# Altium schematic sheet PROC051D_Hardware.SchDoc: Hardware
size 431 x 279 mm; Date: Not shown in title block; ApprovedBy: Not shown in title block; CheckedBy: Not shown in title block; Author: Not shown in title block; CompanyName: Not shown in title block; Engineer: Not shown in title block; Organization: Not shown in title block; Address1: Not shown in title block; Address2: Not shown in title block; Address3: Not shown in title block; Address4: Not shown in title block; DocumentNumber: 16; Revision: Use project parameter SCH_Rev; SheetNumber: 16; SheetTotal: 16; PageSetup: Record=PageOptions¦CenterHorizontal=True¦CenterVertical=True¦PrintScale=1.00¦XCorrection=1.00¦YCorrection=1.00¦PrintKind=0¦BorderSize=5000000¦LeftOffset=0¦BottomOffset=0¦Orientation=2¦PaperLength=1000¦PaperWidth=1000¦Scale=100¦PaperSource=15¦PrintQuality=600¦MediaType=1¦DitherType=10¦PaperKind=Letter¦PrintScaleMode=1
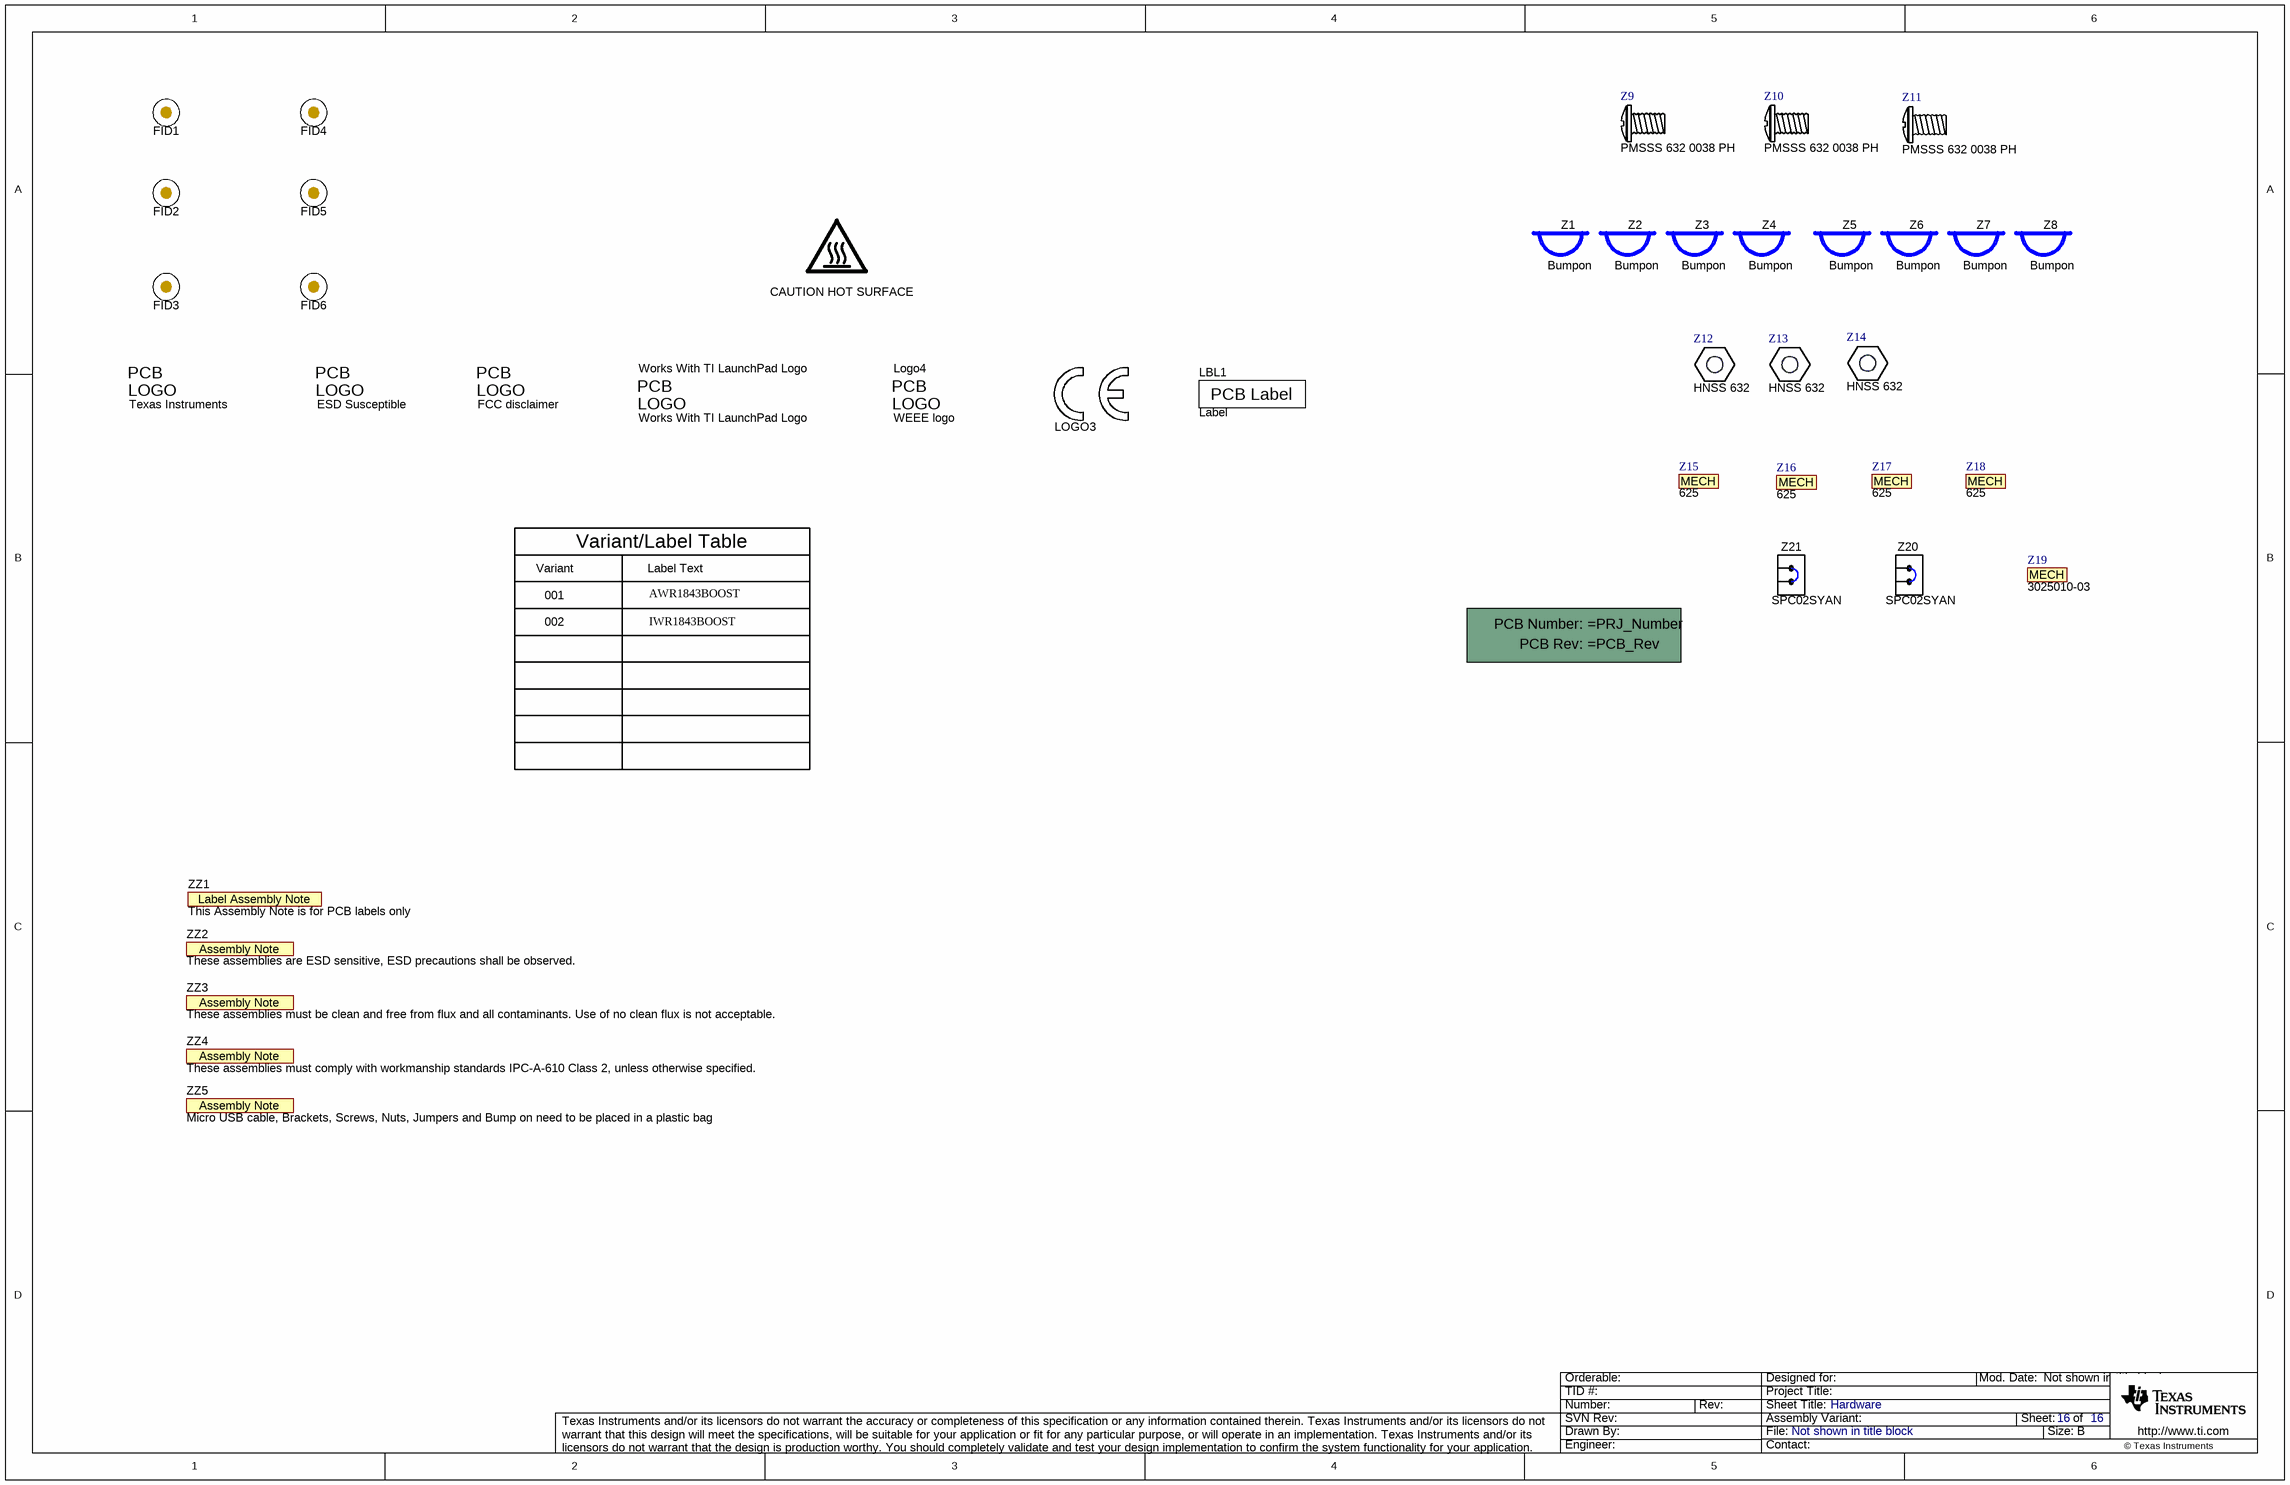
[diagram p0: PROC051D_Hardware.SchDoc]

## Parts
!PCB  PROC051  (value not drawn)  (mechanical)
CAUTION_HOT_SURFACE  CAUTION HOT SURFACE  [IEC_HotSurface_Small]  (no BOM)
ESD_Susceptible  ESD Susceptible  [ESD_Overlay_Small]  (no BOM)
FID1  Fiducial  [Fiducial10-20]  (value not drawn)
FID2  Fiducial  [Fiducial10-20]  (value not drawn)
FID3  Fiducial  [Fiducial10-20]  (value not drawn)
FID4  Fiducial  [Fiducial10-20]  (value not drawn)
FID5  Fiducial  [Fiducial10-20]  (value not drawn)
FID6  Fiducial  [Fiducial10-20]  (value not drawn)
LBL1  Label  [Label_650x200]
Logo1  Texas Instruments  [TI_Stacked_Overlay_Small]  (no BOM)
Logo2  FCC disclaimer  [FCC_disclaimer]  (no BOM)
LOGO3  CE Mark  [CE_Mark_5mm]  (value not drawn)  (no BOM)
Logo4  WEEE logo  [WEEE_Minimum]  (no BOM)
Works_With_TI_LaunchPad_Logo  Works With TI LaunchPad Logo  [WorksWithTILaunchPad]  (graphical)
Z1  Bumpon  [Bumpon_SJ61A1]  (mechanical)
Z2  Bumpon  [Bumpon_SJ61A1]  (mechanical)
Z3  Bumpon  [Bumpon_SJ61A1]  (mechanical)
Z4  Bumpon  [Bumpon_SJ61A1]  (mechanical)
Z5  Bumpon  [Bumpon_SJ61A1]  (mechanical)
Z6  Bumpon  [Bumpon_SJ61A1]  (mechanical)
Z7  Bumpon  [Bumpon_SJ61A1]  (mechanical)
Z8  Bumpon  [Bumpon_SJ61A1]  (mechanical)
Z9  PMSSS 632 0038 PH  [B-F_PMSSS_632_0038_PH]  (mechanical)
Z10  PMSSS 632 0038 PH  [B-F_PMSSS_632_0038_PH]  (mechanical)
Z11  PMSSS 632 0038 PH  [B-F_PMSSS_632_0038_PH]  (mechanical)
Z12  HNSS 632  [B-F_HNSS-632]  (mechanical)
Z13  HNSS 632  [B-F_HNSS-632]  (mechanical)
Z14  HNSS 632  [B-F_HNSS-632]  (mechanical)
Z15  625  (mechanical)
Z16  625  (mechanical)
Z17  625  (mechanical)
Z18  625  (mechanical)
Z19  3025010-03  (mechanical)
Z20  SPC02SYAN  [SPC02SYAN]  (mechanical)
Z21  SPC02SYAN  [SPC02SYAN]  (mechanical)
ZZ1  This Assembly Note is for PCB labels only  [AssemblyNoteLabel]  (no BOM)
ZZ2  These assemblies are ESD sensitive, ESD precautions shall be observed.  [AssemblyNote]  (no BOM)
ZZ3  These assemblies must be clean and free from flux and all contaminants. Use of no clean flux is not acceptable.  [AssemblyNote]  (no BOM)
ZZ4  These assemblies must comply with workmanship standards IPC-A-610 Class 2, unless otherwise specified.  [AssemblyNote]  (no BOM)
ZZ5  Micro USB cable, Brackets, Screws, Nuts, Jumpers and Bump on need to be placed in a plastic bag  [AssemblyNote]  (no BOM)

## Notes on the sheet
- Variant
- Variant/Label Table
- Label Text
- 001
- 002
- AWR1843BOOST
- IWR1843BOOST

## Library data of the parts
!PCB = CMP-0003618-2: Printed Circuit Board; Manufacturer: Any; CompType: PCB
CAUTION_HOT_SURFACE = CMP-0074837-1: IEC 61010-1 Hot Surface Warning; Library Reference: IEC_HotSurface; SymbolCreator: a0412235
ESD_Susceptible = CMP-0074840-1: ESD Susceptible Symbol; Library Reference: Logo; SymbolCreator: a0412235; Lib Reference: ESD_Susceptible
FID1-FID6 = CMP-0077181-1: Fiducial mark.  There is nothing to buy or mount.
LBL1 = CMP-0003625-1: Thermal Transfer Printable Labels, 0.650" W x 0.200" H - 10,000 per roll; Manufacturer: Brady; PartNumber: THT-14-423-10; Note: Size: 0.65" x 0.20 "
Logo1 = CMP-0074838-1: Texas Instrument Corporate Signature; SymbolCreator: a0412235; Lib Reference: TI_Logo; Library Reference: Logo
Logo2 = CMP-0074847-1: FCC_disclaimer; Library Reference: Logo
LOGO3 = CMP-0074844-1: SymbolCreator: a0412235
Logo4 = CMP-0074769-1
Works_With_TI_LaunchPad_Logo = CMP-0077108-1
Z1-Z8 = CMP-0003621-1: Bumpon, Cylindrical, 0.312 X 0.200, Black; Manufacturer: 3M; PartNumber: SJ61A1
Z9-Z11 = CMP-0003820-1: MACHINE SCREW PAN PHILLIPS 6-32; Manufacturer: B&F Fastener Supply; Note: Symbol and footprint updated; CompType: Hardware
Z12-Z14 = CMP-0067637-3: Nut, Hex, 5/16", Stainless Steel, 6-32; Manufacturer: B&F Fastener Supply
Z15-Z18 = CMP-0085300-1: Aluminum Mounting Bracket; Manufacturer: Keystone
Z19 = CMP-0085299-1: Cable, USB A Male to Micro B Male 3'; Manufacturer: Qualtek Electronics Corporation
Z20 Z21 = CMP-0003642-1: Shunt, 100mil, Flash Gold, Black; Manufacturer: Sullins Connector Solutions; Value: 1x2; Note: You can "mate" this to a header by matching the designator.  i.e. use SH-J3 for header J3
ZZ1 = CMP-0003616-3
ZZ2 = CMP-0077236-1
ZZ3 = CMP-0077237-1
ZZ4 = CMP-0077238-1
ZZ5 = AssemblyNote: SymbolCreator: codlsc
